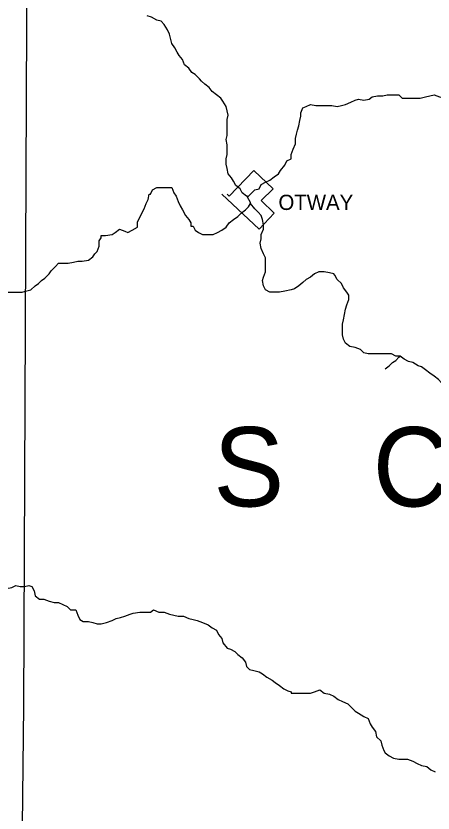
# Model space of a CAD drawing. Extents: x 0 to 40.2, y 0 to 22.
# Drawn here: x 5.056 to 5.589, y 16.218 to 17.238 of the extents above; entities that cross this region are included whole.
import ezdxf

# ---------------------------------------------------------------- set-up
doc = ezdxf.new("R2010")
doc.units = 0
doc.layers.add('Default', color=7, linetype='Continuous')
doc.layers.add('TR_Turning_Path1', color=7, linetype='Continuous')

msp = doc.modelspace()

# ---------------------------------------------------------------- linework, layer by layer
at = {"layer": 'Default'}
for points in [[(5.0668, 17.6697), (5.0708, 17.4025), (5.0695, 17.228), (5.0654, 16.3554), (5.064, 16.2013), (5.0613, 15.8864)], [(5.2931, 17.1543), (5.2904, 17.1571), (5.2849, 17.1625), (5.2808, 17.1652), (5.2767, 17.1707), (5.2713, 17.1748), (5.2685, 17.1816), (5.2645, 17.1871), (5.2617, 17.1911), (5.259, 17.1966), (5.2549, 17.2021), (5.2535, 17.2089), (5.2522, 17.2143), (5.2495, 17.2198), (5.2454, 17.2266), (5.2413, 17.2307), (5.2358, 17.232), (5.229, 17.2361), (5.2236, 17.2375)], [(5.3517, 17.0057), (5.3517, 17.0071), (5.3503, 17.0071), (5.3449, 17.0112), (5.3422, 17.0166), (5.3367, 17.0207), (5.334, 17.0262), (5.3313, 17.0303), (5.3272, 17.0357), (5.3258, 17.0425), (5.3244, 17.048), (5.3244, 17.0548), (5.3258, 17.0603), (5.3258, 17.0671), (5.3258, 17.0725), (5.3244, 17.0793), (5.3258, 17.0848), (5.3258, 17.0916), (5.3258, 17.0971), (5.3258, 17.1052), (5.3272, 17.1107), (5.3258, 17.1162), (5.3244, 17.1216), (5.3204, 17.1284), (5.3176, 17.1325), (5.3122, 17.1366), (5.3067, 17.1407), (5.3026, 17.1462), (5.2972, 17.1502), (5.2931, 17.1543)], [(5.4199, 17.1134), (5.4226, 17.1202), (5.4267, 17.1216), (5.4322, 17.1243), (5.439, 17.123), (5.4458, 17.123), (5.4526, 17.123), (5.4594, 17.123), (5.4662, 17.1216), (5.4717, 17.123), (5.4771, 17.1243), (5.484, 17.1271), (5.4894, 17.1298), (5.4935, 17.1312), (5.5003, 17.1298), (5.5071, 17.1312), (5.5112, 17.1339), (5.518, 17.1352), (5.5249, 17.1352), (5.5303, 17.1366), (5.5385, 17.1366), (5.5453, 17.1366), (5.5494, 17.1325), (5.5562, 17.1325), (5.5576, 17.1325), (5.5603, 17.1325)], [(5.5603, 17.1325), (5.5658, 17.1325), (5.5726, 17.1325), (5.5794, 17.1339), (5.5849, 17.1352), (5.5903, 17.1366), (5.5971, 17.1339), (5.6039, 17.1325), (5.608, 17.1284), (5.6149, 17.1271), (5.6203, 17.1257), (5.6285, 17.1243), (5.6339, 17.123), (5.6394, 17.123), (5.6462, 17.1216), (5.6503, 17.1202), (5.653, 17.1134), (5.653, 17.1066), (5.6544, 17.0998), (5.6558, 17.0971), (5.6558, 17.0971)], [(5.3517, 17.0057), (5.3558, 17.0098), (5.3613, 17.0153), (5.3667, 17.0166), (5.3694, 17.0221), (5.3749, 17.0248), (5.3803, 17.0275), (5.3858, 17.0316), (5.3913, 17.0357), (5.394, 17.0398), (5.3994, 17.0466), (5.4022, 17.0521), (5.4076, 17.0548), (5.4076, 17.0603), (5.4103, 17.0671), (5.4131, 17.0739), (5.4131, 17.0807), (5.4144, 17.0862), (5.4158, 17.0916), (5.4172, 17.0971), (5.4185, 17.1039), (5.4199, 17.1093), (5.4199, 17.1134), (5.4199, 17.1134)], [(5.3258, 17.0098), (5.3285, 17.0071), (5.3599, 17.0398), (5.3844, 17.0166), (5.3694, 17.0016), (5.3858, 16.9853), (5.3667, 16.9648), (5.319, 17.0098)], [(5.2276, 17.0098), (5.2304, 17.0153), (5.2358, 17.018), (5.2413, 17.018), (5.2467, 17.018), (5.2549, 17.018), (5.2576, 17.0112), (5.2604, 17.0071), (5.2631, 17.0003), (5.2658, 16.9948), (5.2685, 16.9894), (5.2726, 16.9825), (5.2767, 16.9771), (5.2795, 16.973), (5.2795, 16.9689), (5.2822, 16.9689)], [(5.1649, 16.9566), (5.1704, 16.9566), (5.1786, 16.958), (5.1826, 16.9607), (5.1881, 16.9648), (5.1949, 16.9621), (5.199, 16.9607), (5.2045, 16.9635), (5.2113, 16.9675), (5.2113, 16.9744), (5.214, 16.9798), (5.2167, 16.9853), (5.2195, 16.9907), (5.2222, 16.9975), (5.2249, 17.003), (5.2263, 17.0098), (5.2276, 17.0098)], [(5.3558, 16.9975), (5.3558, 16.9989), (5.3517, 17.0057)], [(5.3558, 16.9975), (5.3558, 16.9989), (5.3517, 17.0057)], [(5.2822, 16.9689), (5.2849, 16.9635), (5.289, 16.9607), (5.2944, 16.958), (5.3013, 16.958), (5.3081, 16.958), (5.3135, 16.9607), (5.319, 16.9635), (5.3244, 16.9675), (5.3285, 16.973), (5.334, 16.9771), (5.3394, 16.9812), (5.3435, 16.9853), (5.349, 16.9894), (5.3531, 16.9934), (5.3558, 16.9975)], [(5.4635, 16.9062), (5.4635, 16.9062), (5.4621, 16.9076), (5.4621, 16.9076), (5.4567, 16.9089), (5.4499, 16.9103), (5.4431, 16.9103), (5.4376, 16.9076), (5.4322, 16.9035), (5.4267, 16.9007), (5.4226, 16.8966), (5.4172, 16.8926), (5.4117, 16.8885), (5.4076, 16.8871), (5.3994, 16.8857), (5.3926, 16.8844), (5.3872, 16.8844), (5.3803, 16.8844), (5.3749, 16.8871), (5.3722, 16.8926), (5.3708, 16.8994), (5.3722, 16.9035), (5.3749, 16.9103), (5.3749, 16.9157), (5.3749, 16.9212), (5.3749, 16.928), (5.3722, 16.9335), (5.3694, 16.9403), (5.3681, 16.9471), (5.3694, 16.9525), (5.3694, 16.958), (5.3722, 16.9648), (5.3722, 16.9703), (5.3708, 16.9771), (5.3694, 16.9825), (5.3653, 16.9866), (5.3613, 16.9907), (5.3558, 16.9975)], [(5.0681, 16.8857), (5.0749, 16.8871), (5.0804, 16.8926), (5.0845, 16.8953), (5.0886, 16.8994), (5.0927, 16.9021), (5.0981, 16.9076), (5.1008, 16.9116), (5.1063, 16.9171), (5.1104, 16.9212), (5.1158, 16.9212), (5.1227, 16.9212), (5.1295, 16.9226), (5.1349, 16.9239), (5.1404, 16.9239), (5.1486, 16.9253), (5.154, 16.9294), (5.1567, 16.9335), (5.1595, 16.9362), (5.1622, 16.943), (5.1622, 16.9498), (5.1649, 16.9539), (5.1649, 16.9566), (5.1649, 16.9566)], [(5.5167, 16.8053), (5.5153, 16.8053), (5.5126, 16.8053), (5.5058, 16.8053), (5.5003, 16.8067), (5.4962, 16.8108), (5.4894, 16.8135), (5.4826, 16.8148), (5.4771, 16.8189), (5.4744, 16.8244), (5.4731, 16.8298), (5.4731, 16.8367), (5.4731, 16.8435), (5.4744, 16.8489), (5.4758, 16.8557), (5.4771, 16.8626), (5.4785, 16.868), (5.4812, 16.8748), (5.4812, 16.8803), (5.4785, 16.8844), (5.4744, 16.8898), (5.4717, 16.8953), (5.4662, 16.9007), (5.4635, 16.9062)], [(5.0231, 16.8844), (5.0259, 16.8885), (5.0313, 16.8871), (5.0395, 16.8857), (5.0449, 16.8844), (5.0504, 16.8844), (5.0572, 16.8844), (5.064, 16.8844), (5.0681, 16.8857), (5.0681, 16.8857)], [(5.5467, 16.8026), (5.5412, 16.8026), (5.5358, 16.8053), (5.5303, 16.8053), (5.5221, 16.8053), (5.5167, 16.8053)], [(5.5276, 16.7862), (5.533, 16.7903), (5.5371, 16.7944), (5.5412, 16.7971), (5.5453, 16.8012), (5.5467, 16.8026)], [(5.623, 16.7521), (5.6217, 16.7535), (5.6203, 16.7535), (5.6135, 16.7562), (5.6094, 16.7603), (5.6039, 16.7644), (5.5999, 16.7685), (5.5958, 16.7726), (5.5903, 16.7767), (5.5849, 16.7808), (5.5794, 16.7848), (5.574, 16.7889), (5.5699, 16.7903), (5.563, 16.7944), (5.5576, 16.7958), (5.5521, 16.7985), (5.5467, 16.8026)], [(5.0081, 16.5163), (5.0136, 16.5163), (5.0177, 16.5122), (5.0231, 16.5108), (5.0286, 16.5067), (5.034, 16.5026), (5.0395, 16.5013), (5.0436, 16.5053), (5.0504, 16.5067), (5.0559, 16.5094), (5.0613, 16.5081), (5.064, 16.5081), (5.0668, 16.5081)], [(5.0668, 16.5081), (5.0722, 16.5094), (5.0763, 16.5081), (5.079, 16.5026), (5.0804, 16.4958), (5.0858, 16.4917), (5.0913, 16.4917), (5.0981, 16.489), (5.1049, 16.4876), (5.1104, 16.4876), (5.1158, 16.4849), (5.1213, 16.4822), (5.1254, 16.4781), (5.1322, 16.4781), (5.1349, 16.4713), (5.1377, 16.4658), (5.1417, 16.4631), (5.1486, 16.4631), (5.154, 16.4617), (5.154, 16.4617)], [(5.154, 16.4617), (5.1595, 16.4604), (5.1649, 16.4604), (5.1717, 16.4617), (5.1786, 16.4644), (5.184, 16.4672), (5.1895, 16.4685), (5.1949, 16.4699), (5.2017, 16.4726), (5.2058, 16.474), (5.214, 16.4753), (5.2208, 16.4753), (5.2276, 16.4753), (5.2317, 16.4781), (5.2385, 16.4753), (5.2454, 16.4753), (5.2522, 16.4726), (5.2576, 16.4713), (5.2631, 16.4699), (5.2699, 16.4699), (5.2767, 16.4672), (5.2822, 16.4658), (5.2876, 16.4644), (5.2944, 16.4617), (5.3013, 16.459), (5.3013, 16.459), (5.3013, 16.459)], [(5.3013, 16.459), (5.3067, 16.4549), (5.3122, 16.4522), (5.3149, 16.4467), (5.319, 16.4413), (5.3204, 16.4358), (5.3258, 16.429), (5.3299, 16.4276), (5.3354, 16.4249), (5.3394, 16.4208), (5.3449, 16.4167), (5.349, 16.4113), (5.3503, 16.4058), (5.3544, 16.4017), (5.3599, 16.4004), (5.3667, 16.399), (5.3708, 16.3963), (5.3763, 16.3922), (5.3831, 16.3881), (5.3872, 16.3854), (5.3926, 16.3813), (5.3981, 16.3772), (5.4035, 16.3745), (5.4076, 16.3731), (5.4076, 16.3717)], [(5.4076, 16.3717), (5.4131, 16.3717), (5.4199, 16.3717), (5.4253, 16.3717), (5.4322, 16.3717), (5.4376, 16.3731), (5.4444, 16.3758), (5.4499, 16.3717), (5.4567, 16.3704), (5.4621, 16.3676), (5.4676, 16.3635), (5.4731, 16.3608), (5.4799, 16.3581), (5.484, 16.354), (5.4894, 16.3486), (5.4935, 16.3458), (5.5003, 16.3417), (5.5058, 16.339), (5.5085, 16.3322), (5.5112, 16.3281), (5.5153, 16.3226), (5.5167, 16.3158), (5.5221, 16.3104), (5.5235, 16.3049), (5.5262, 16.2981), (5.5276, 16.2954)], [(5.5276, 16.2954), (5.533, 16.2913), (5.5385, 16.2886), (5.5453, 16.2872), (5.5508, 16.2872), (5.5562, 16.2872), (5.563, 16.2845), (5.5685, 16.2817), (5.574, 16.279), (5.5808, 16.2777), (5.5862, 16.2736), (5.5917, 16.2708)]]:
    msp.add_lwpolyline(points, dxfattribs=at)
msp.add_spline([(6.6647, 15.66), (6.6347, 15.6791), (6.6101, 15.6982), (6.5788, 15.7227), (6.5583, 15.7596), (6.5447, 15.795), (6.5324, 15.8264), (6.5229, 15.8727), (6.5174, 15.9123), (6.5174, 15.9545), (6.5174, 15.9927), (6.5147, 16.0445), (6.5011, 16.0854), (6.4902, 16.1195), (6.4738, 16.1454), (6.4574, 16.1645), (6.4493, 16.1918), (6.4493, 16.234), (6.4629, 16.2695), (6.4724, 16.3117), (6.4724, 16.3554), (6.4656, 16.3976), (6.4629, 16.4385), (6.4465, 16.4685), (6.4288, 16.4849), (6.4015, 16.4999), (6.3852, 16.5026), (6.3593, 16.4944), (6.3456, 16.4917), (6.3102, 16.4822), (6.2734, 16.474), (6.2393, 16.4576), (6.212, 16.4385), (6.1861, 16.4222), (6.1548, 16.4045), (6.1289, 16.3895), (6.1098, 16.3785), (6.0866, 16.3704), (6.0511, 16.3717), (6.0171, 16.3785), (5.983, 16.3813), (5.9448, 16.3881), (5.9189, 16.3704), (5.8957, 16.3526), (5.8766, 16.3117), (5.8589, 16.2872), (5.8357, 16.2517), (5.8166, 16.2177), (5.7935, 16.2081), (5.7539, 16.1918), (5.7212, 16.1754), (5.6803, 16.1631), (5.653, 16.1481), (5.6162, 16.1318), (5.5944, 16.1018), (5.5821, 16.0772), (5.5685, 16.0418), (5.559, 16.0077), (5.5562, 15.9668), (5.5249, 15.9382), (5.4908, 15.9123), (5.4431, 15.8891), (5.3926, 15.8891), (5.3517, 15.8809), (5.3067, 15.8809), (5.2631, 15.8864), (5.2222, 15.9054), (5.1963, 15.9232), (5.1622, 15.93), (5.1363, 15.9313), (5.1186, 15.915), (5.0845, 15.9041), (5.0613, 15.8864)], degree=3, dxfattribs=at)

# ---------------------------------------------------------------- texts
msp.add_text('OTWAY', height=0.0195, dxfattribs=at).set_placement((5.3913, 16.9894))
at = {"layer": 'TR_Turning_Path1'}
msp.add_text('S   C   I   O   T   O', height=0.101489, dxfattribs=at).set_placement((5.3081, 16.6103))

doc.saveas('drawing.dxf')
